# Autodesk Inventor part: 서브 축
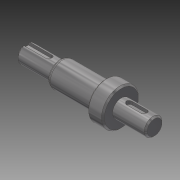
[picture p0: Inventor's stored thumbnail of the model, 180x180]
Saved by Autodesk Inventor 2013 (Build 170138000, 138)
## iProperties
Created: 2016-04
Part Number: 서브 축
Document SubType Name: Modeling
Designer: mdu
Density: 1 g/cm^3
Mass: 19.9624 g
Surface Area: 57.7178 cm^2
Volume: 19.9624 cm^3
Material: 강철, 연강
Author: mdu
Revision Number: 1
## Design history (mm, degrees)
sketch "스케치1"
  geometry: L1 (-16.331, 0)-(-103.831, 0); L2 (-16.331, 0)-(-16.331, -6); L3 (-16.331, -6)-(-38.831, -6); L4 (-38.831, -12.5)-(-46.5, -12.5); L5 (-46.5, -8.5)-(-79.013, -8.5); L6 (-103.831, -6)-(-103.831, 0); L7 (-46.5, -8.5)-(-46.5, -12.5); L8 (-38.831, -6)-(-38.831, -12.5); L9 (-46.5, 12.249)-(-46.5, -12.249) reference; L10 (-38.831, -17)-(-38.831, 17) reference; L11 (-103.831, -6)-(-80.831, -6); L12 (-80.831, -6)-(-80.831, -7.45); L13 (-80.831, -7.45)-(-79.013, -8.5); 2 further points
  constraints: 23 end point, 6 perpendicular, 2 collinear, 2 parallel, 1 horizontal, 1 midpoint, 1 point on line
  dimensions: "d1" = 12 diameter of L3 L1; "d2" = 25 diameter of L4 L1; "d3" = 17 diameter of L5 L1; "d18" = 22.5 distance of L2.end L3.end; "d20" = 65 distance between parallel lines of L6 L8; "d21" = 7.66872 distance of L4.start L4.end (derived); "d28" = 12 diameter of L11 L1; "d29" = 23 distance of L6.start L11.end; "d30" = 14.9 diameter of L12.end L1; "d32" = 30 deg angle of L5 L13
revolve "회전1" sketch "스케치1" stored, may be unused: angle "d5" = 90 deg
chamfer "모따기1" distance "d6" = 1; stored, may be unused: second distance "d7" = 2, angle "d8" = 45 deg
node "작업 평면1"
sketch "스케치2"
  geometry: L1 (11.25, 5)-(11.25, -5) reference; L2 (-5.75, -2)-(4.25, -2); L3 (4.25, 2)-(-5.75, 2); A1 r 2 centre (4.25, 0) between (4.25, -2) and (4.25, 2); A2 r 2 centre (-5.75, 0) between (-5.75, 2) and (-5.75, -2); 2 further points
  constraints: 4 end point, 4 point on circle, 4 tangent, 2 centre point, 1 horizontal alignment, 1 midpoint, 1 parallel, 1 perpendicular
  dimensions: "d9" = 4 distance between parallel lines of L2 L3; "d10" = 14 dimension on A1 A2; "d11" = 5 distance edge to line of A1 L1
extrude "돌출1" cut sketch "스케치2" distance "d12" = 2.5; taper "d13" = 0 deg
node "작업 평면2"
sketch "스케치3"
  geometry: L1 (-103.831, -5)-(-103.831, 5) reference; L2 (-103.831, 2)-(-87.831, 2); L3 (-87.831, -2)-(-103.831, -2); A1 r 2 centre (-87.831, 0) between (-87.831, -2) and (-87.831, 2); 2 further points
  constraints: 4 end point, 2 perpendicular, 2 point on circle, 2 point on line, 2 tangent, 1 centre point, 1 horizontal alignment, 1 midpoint
  dimensions: "d14" = 4 distance between parallel lines of L3 L2; "d15" = 18 dimension on A1 L1
extrude "돌출2" cut sketch "스케치3" distance "d16" = 2.5; taper "d17" = 0 deg
sketch "스케치4"
  geometry: C1 r 12.5 at (0, 0) reference; 1 further point
extrude "돌출3" join sketch "스케치4" distance "d22" = 3; taper "d23" = 0 deg
chamfer "모따기2" distance "d24" = 1; stored, may be unused: second distance "d25" = 2, angle "d26" = 45 deg
fillet "모깎기1" dims "d34" = 1
fillet "모깎기2" dims "d35" = 2
node "솔리드1"
node "참조4"
node "참조5"
other parameters: "d33" = 6
